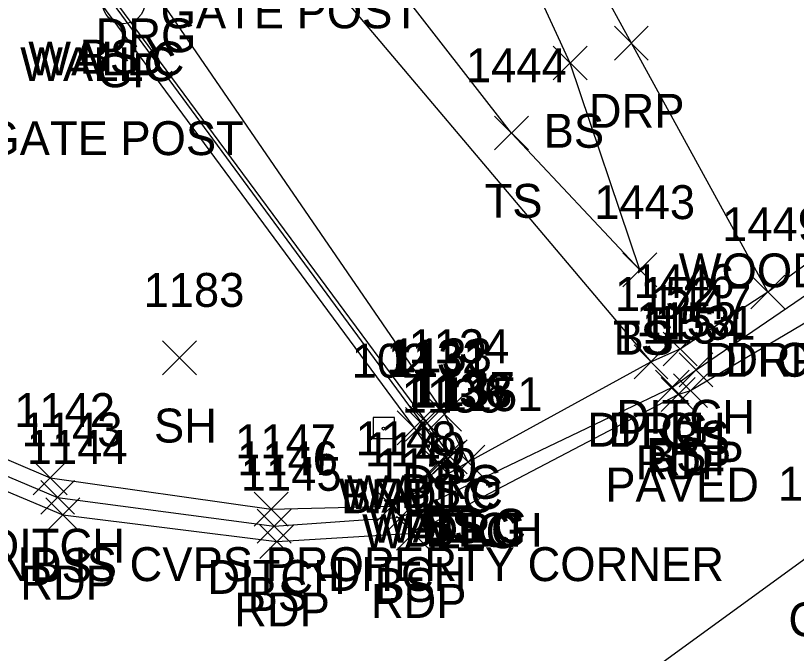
# Model space of a CAD drawing. Extents: x 1647133 to 1649138, y 411736 to 414924.
# Drawn here: x 1648764.25 to 1648810.32, y 412065.88 to 412103.5 of the extents above; entities that cross this region are included whole.
import ezdxf

# ---------------------------------------------------------------- set-up
doc = ezdxf.new("R2010")
doc.units = 0
for name, color, linetype in [('D_A', 7, 'Continuous'), ('D_C', 7, 'Continuous'), ('D_I', 7, 'Continuous'), ('D_TIC', 7, 'Continuous'), ('DD', 7, 'Continuous'), ('L_A', 7, 'Continuous'), ('L_I', 7, 'Continuous'), ('L_TIC', 7, 'Continuous'), ('LELB', 7, 'Continuous'), ('Level 18', 7, 'Continuous'), ('LW', 7, 'Continuous'), ('M_A', 7, 'Continuous'), ('M_C', 7, 'Continuous'), ('M_I', 7, 'Continuous'), ('P_A', 7, 'Continuous'), ('P_I', 7, 'Continuous'), ('P_TIC', 7, 'Continuous'), ('PET', 7, 'Continuous'), ('PRC', 7, 'Continuous'), ('R_A', 7, 'Continuous'), ('R_C', 7, 'Continuous'), ('R_I', 7, 'Continuous'), ('R_TIC', 7, 'Continuous'), ('RDG', 7, 'Continuous'), ('RDP', 7, 'Continuous'), ('RGP', 7, 'Continuous')]:
    doc.layers.add(name, color=color, linetype=linetype)

msp = doc.modelspace()

# ---------------------------------------------------------------- linework, layer by layer
at = {"layer": 'D_TIC'}
for points in [[(1648807.637, 412086.198), (1648809.637, 412088.198)], [(1648809.637, 412086.198), (1648807.637, 412088.198)], [(1648802.463, 412082.836), (1648804.463, 412084.836)], [(1648804.463, 412082.836), (1648802.463, 412084.836)], [(1648802.463, 412082.836), (1648804.463, 412084.836)], [(1648804.463, 412082.836), (1648802.463, 412084.836)], [(1648800.739, 412082.078), (1648802.739, 412084.078)], [(1648802.739, 412082.078), (1648800.739, 412084.078)], [(1648800.739, 412082.078), (1648802.739, 412084.078)], [(1648802.739, 412082.078), (1648800.739, 412084.078)], [(1648789.942, 412076.169), (1648791.942, 412078.169)], [(1648791.942, 412076.169), (1648789.942, 412078.169)], [(1648765.293, 412075.231), (1648767.293, 412077.231)], [(1648767.293, 412075.231), (1648765.293, 412077.231)], [(1648785.441, 412073.562), (1648787.441, 412075.562)], [(1648787.441, 412073.562), (1648785.441, 412075.562)], [(1648778.329, 412073.391), (1648780.329, 412075.391)], [(1648780.329, 412073.391), (1648778.329, 412075.391)]]:
    msp.add_lwpolyline(points, dxfattribs=at)
at = {"layer": 'DD'}
for points in [[(1648700.204, 412133.762), (1648700.854, 412134.053), (1648701.48, 412134.614), (1648714.403, 412119.84), (1648734.341, 412097.427), (1648745.316, 412087.535), (1648753.692, 412081.611), (1648766.293, 412076.231), (1648779.329, 412074.391), (1648786.441, 412074.562), (1648790.942, 412077.169), (1648801.739, 412083.078)], [(1648803.463, 412083.836), (1648808.637, 412087.198), (1648813.917, 412091.05), (1648819.325, 412099.049)], [(1648801.739, 412083.078), (1648803.463, 412083.836)]]:
    msp.add_lwpolyline(points, dxfattribs=at)
at = {"layer": 'L_TIC'}
for points in [[(1648795.966, 412099.703), (1648797.966, 412101.703)], [(1648797.966, 412099.703), (1648795.966, 412101.703)], [(1648792.512, 412095.572), (1648794.512, 412097.572)], [(1648794.512, 412095.572), (1648792.512, 412097.572)], [(1648800.085, 412087.497), (1648802.085, 412089.497)], [(1648802.085, 412087.497), (1648800.085, 412089.497)], [(1648800.085, 412087.497), (1648802.085, 412089.497)], [(1648802.085, 412087.497), (1648800.085, 412089.497)], [(1648772.924, 412082.319), (1648774.924, 412084.319)], [(1648774.924, 412082.319), (1648772.924, 412084.319)], [(1648803.397, 412081.609), (1648805.397, 412083.609)], [(1648805.397, 412081.609), (1648803.397, 412083.609)], [(1648803.397, 412081.609), (1648805.397, 412083.609)], [(1648805.397, 412081.609), (1648803.397, 412083.609)], [(1648802.001, 412080.585), (1648804.001, 412082.585)], [(1648804.001, 412080.585), (1648802.001, 412082.585)], [(1648802.001, 412080.585), (1648804.001, 412082.585)], [(1648804.001, 412080.585), (1648802.001, 412082.585)], [(1648786.771, 412078.188), (1648788.771, 412080.188)], [(1648788.771, 412078.188), (1648786.771, 412080.188)], [(1648787.252, 412078.392), (1648789.252, 412080.392)], [(1648789.252, 412078.392), (1648787.252, 412080.392)], [(1648787.529, 412078.455), (1648789.529, 412080.455)], [(1648789.529, 412078.455), (1648787.529, 412080.455)], [(1648788.611, 412076.412), (1648790.611, 412078.412)], [(1648790.611, 412076.412), (1648788.611, 412078.412)], [(1648788.611, 412076.412), (1648790.611, 412078.412)], [(1648790.611, 412076.412), (1648788.611, 412078.412)], [(1648788.743, 412076.373), (1648790.743, 412078.373)], [(1648790.743, 412076.373), (1648788.743, 412078.373)], [(1648788.895, 412076.48), (1648790.895, 412078.48)], [(1648790.895, 412076.48), (1648788.895, 412078.48)], [(1648788.161, 412076.085), (1648790.161, 412078.085)], [(1648790.161, 412076.085), (1648788.161, 412078.085)], [(1648765.731, 412074.085), (1648767.731, 412076.085)], [(1648767.731, 412074.085), (1648765.731, 412076.085)], [(1648785.989, 412072.92), (1648787.989, 412074.92)], [(1648787.989, 412072.92), (1648785.989, 412074.92)], [(1648778.502, 412072.38), (1648780.502, 412074.38)], [(1648780.502, 412072.38), (1648778.502, 412074.38)]]:
    msp.add_lwpolyline(points, dxfattribs=at)
at = {"layer": 'LELB'}
for points in [[(1648745.05, 412138.635), (1648769.584, 412105.08), (1648788.529, 412079.455), (1648789.895, 412077.48), (1648789.743, 412077.373)], [(1648700.854, 412134.053), (1648713.799, 412119.311), (1648733.781, 412096.829), (1648744.747, 412086.599), (1648753.939, 412080.489), (1648766.731, 412075.085), (1648779.502, 412073.38), (1648786.989, 412073.92), (1648803.001, 412081.585)], [(1648801.085, 412088.497), (1648796.966, 412100.703), (1648790.38, 412115.008), (1648781.189, 412119.025)], [(1648801.085, 412088.497), (1648793.512, 412096.572), (1648781.967, 412111.414), (1648776.578, 412115.68)], [(1648804.397, 412082.609), (1648816.422, 412090.813), (1648820.622, 412097.822)], [(1648803.001, 412081.585), (1648804.397, 412082.609)]]:
    msp.add_lwpolyline(points, dxfattribs=at)
at = {"layer": 'Level 18'}
for p, q in [((1648786.605, 412079.803), (1648785.355, 412079.803)), ((1648785.355, 412079.803), (1648785.355, 412078.553)), ((1648786.605, 412079.803), (1648785.355, 412079.803)), ((1648785.355, 412079.803), (1648785.355, 412078.553)), ((1648786.605, 412078.553), (1648786.605, 412079.803)), ((1648786.605, 412078.553), (1648786.605, 412079.803)), ((1648785.355, 412078.553), (1648786.605, 412078.553)), ((1648785.355, 412078.553), (1648786.605, 412078.553))]:
    msp.add_line(p, q, dxfattribs=at)
msp.add_circle((1648785.956, 412079.14), 0.0833, dxfattribs=at)
at = {"layer": 'LW'}
for points in [[(1648745.173, 412138.304), (1648744.678, 412137.988), (1648768.983, 412104.635), (1648787.771, 412079.188), (1648789.161, 412077.085), (1648789.611, 412077.412)], [(1648745.173, 412138.304), (1648769.46, 412104.966), (1648788.252, 412079.392), (1648789.611, 412077.412)]]:
    msp.add_lwpolyline(points, dxfattribs=at)
at = {"layer": 'P_TIC'}
for points in [[(1648802.342, 412080.153), (1648804.342, 412082.153)], [(1648804.342, 412080.153), (1648802.342, 412082.153)], [(1648802.342, 412080.153), (1648804.342, 412082.153)], [(1648804.342, 412080.153), (1648802.342, 412082.153)], [(1648803.077, 412080.379), (1648805.077, 412082.379)], [(1648805.077, 412080.379), (1648803.077, 412082.379)], [(1648803.077, 412080.379), (1648805.077, 412082.379)], [(1648805.077, 412080.379), (1648803.077, 412082.379)], [(1648766.034, 412073.054), (1648768.034, 412075.054)], [(1648768.034, 412073.054), (1648766.034, 412075.054)], [(1648786.719, 412071.973), (1648788.719, 412073.973)], [(1648788.719, 412071.973), (1648786.719, 412073.973)], [(1648778.661, 412071.471), (1648780.661, 412073.471)], [(1648780.661, 412071.471), (1648778.661, 412073.471)]]:
    msp.add_lwpolyline(points, dxfattribs=at)
at = {"layer": 'PET'}
for points in [[(1648646.814, 412192.55), (1648654.671, 412182.929), (1648666.114, 412172.04), (1648681.295, 412155.026), (1648700.204, 412133.762), (1648713.219, 412118.744), (1648733.101, 412096.235), (1648743.955, 412085.872), (1648754.321, 412079.376), (1648767.034, 412074.054), (1648779.661, 412072.471), (1648787.719, 412072.973), (1648803.342, 412081.153)], [(1648804.077, 412081.379), (1648817.165, 412089.126), (1648824.651, 412094.018), (1648832.497, 412099.297), (1648836.674, 412102.355), (1648842.257, 412096.253), (1648847.201, 412090.123), (1648841.152, 412084.448), (1648829.009, 412072.706), (1648818.716, 412064.019)], [(1648803.342, 412081.153), (1648804.077, 412081.379)]]:
    msp.add_lwpolyline(points, dxfattribs=at)
at = {"layer": 'PRC'}
msp.add_lwpolyline([(1648776.375, 412047.027), (1648793.935, 412059.182), (1648811.415, 412071.887), (1648812.617, 412072.528)], dxfattribs=at)
at = {"layer": 'R_TIC'}
for points in [[(1648799.581, 412100.88), (1648801.581, 412102.88)], [(1648801.581, 412100.88), (1648799.581, 412102.88)], [(1648807.637, 412086.198), (1648809.637, 412088.198)], [(1648809.637, 412086.198), (1648807.637, 412088.198)], [(1648800.739, 412082.078), (1648802.739, 412084.078)], [(1648802.739, 412082.078), (1648800.739, 412084.078)], [(1648788.563, 412078.997), (1648790.563, 412080.997)], [(1648790.563, 412078.997), (1648788.563, 412080.997)], [(1648789.942, 412076.169), (1648791.942, 412078.169)], [(1648791.942, 412076.169), (1648789.942, 412078.169)]]:
    msp.add_lwpolyline(points, dxfattribs=at)
at = {"layer": 'RDG'}
for points in [[(1648665.441, 412272.797), (1648687.368, 412235.883), (1648707.36, 412207.822), (1648732.67, 412172.62), (1648752.06, 412147.321), (1648777.802, 412111.4), (1648801.739, 412083.078)], [(1648657.183, 412267.776), (1648679.811, 412230.814), (1648700.282, 412202.253), (1648725.639, 412167.846), (1648744.327, 412141.94), (1648771.48, 412106.331), (1648789.563, 412079.997), (1648790.942, 412077.169)]]:
    msp.add_lwpolyline(points, dxfattribs=at)
at = {"layer": 'RDP'}
msp.add_lwpolyline([(1648808.637, 412087.198), (1648800.581, 412101.88), (1648792.637, 412116.358), (1648777.478, 412142.603), (1648782.888, 412146.657), (1648798.186, 412123.321), (1648809.106, 412109.222), (1648819.325, 412099.049), (1648820.622, 412097.822), (1648822.814, 412097.685)], dxfattribs=at)
at = {"layer": 'RGP'}
msp.add_circle((1648770.622, 412104.27), 1.25, dxfattribs=at)

# ---------------------------------------------------------------- texts
at = {"layer": 'D_A'}
for p in [(1648804.873, 412082.198), (1648799.699, 412078.836), (1648799.699, 412078.836), (1648797.975, 412078.078), (1648797.975, 412078.078), (1648787.178, 412072.169), (1648762.529, 412071.231), (1648775.565, 412069.391), (1648782.678, 412069.562)]:
    msp.add_text('DITCH', height=2, dxfattribs=at).set_placement(p)
at = {"layer": 'D_C'}
msp.add_text('PAVED', height=2, dxfattribs=at).set_placement((1648799.045, 412074.836))
msp.add_text('PAVED', height=2, dxfattribs=at).set_placement((1648799.045, 412074.836))
at = {"layer": 'D_I'}
for s, p in [('1449', (1648805.936, 412090.198)), ('1446', (1648800.715, 412086.836)), ('1446', (1648800.715, 412086.836)), ('1152', (1648799.613, 412086.078)), ('1152', (1648799.613, 412086.078)), ('1151', (1648789.383, 412080.169)), ('1142', (1648764.167, 412079.231)), ('1147', (1648777.203, 412077.391)), ('1148', (1648784.315, 412077.562))]:
    msp.add_text(s, height=2, dxfattribs=at).set_placement(p)
at = {"layer": 'L_A'}
for s, p in [('WALLC', (1648764.996, 412099.966)), ('BS', (1648768.025, 412100.08)), ('WALLC', (1648764.519, 412099.635)), ('BS', (1648795.407, 412095.703)), ('TS', (1648791.921, 412091.572)), ('TS', (1648799.494, 412083.497)), ('BS', (1648799.526, 412083.497)), ('SH', (1648772.413, 412078.319)), ('BS', (1648802.838, 412077.609)), ('BS', (1648802.838, 412077.609)), ('BS', (1648801.442, 412076.585)), ('BS', (1648801.442, 412076.585)), ('WALLC', (1648783.788, 412074.392)), ('BS', (1648786.97, 412074.455)), ('WALLC', (1648783.306, 412074.188)), ('WALLC', (1648784.696, 412072.085)), ('WALLC', (1648785.147, 412072.412)), ('WALLC', (1648785.147, 412072.412)), ('BS', (1648788.184, 412072.373)), ('BS', (1648788.336, 412072.48)), ('BS', (1648765.172, 412070.085)), ('BS', (1648785.43, 412068.92)), ('BS', (1648777.943, 412068.38))]:
    msp.add_text(s, height=2, dxfattribs=at).set_placement(p)
at = {"layer": 'L_I'}
for s, p in [('1444', (1648790.819, 412099.572)), ('1443', (1648798.392, 412091.497)), ('1443', (1648798.392, 412091.497)), ('1183', (1648771.798, 412086.319)), ('1447', (1648801.704, 412085.609)), ('1447', (1648801.704, 412085.609)), ('1153', (1648800.875, 412084.585)), ('1153', (1648800.875, 412084.585)), ('1132', (1648786.126, 412082.392)), ('1133', (1648786.403, 412082.455)), ('1131', (1648786.212, 412082.188)), ('1136', (1648787.43, 412080.412)), ('1136', (1648787.43, 412080.412)), ('1138', (1648787.617, 412080.373)), ('1137', (1648787.769, 412080.48)), ('1135', (1648787.035, 412080.085)), ('1143', (1648764.605, 412078.085)), ('1149', (1648784.855, 412076.92)), ('1146', (1648777.321, 412076.38))]:
    msp.add_text(s, height=2, dxfattribs=at).set_placement(p)
at = {"layer": 'M_A'}
msp.add_text('BND', height=2, dxfattribs=at).set_placement((1648783.442, 412074.145))
at = {"layer": 'M_C'}
msp.add_text('BND IS CVPS PROPERTY CORNER', height=2, dxfattribs=at).set_placement((1648761.316, 412070.145))
at = {"layer": 'M_I'}
msp.add_text('102', height=2, dxfattribs=at).set_placement((1648784.08, 412082.145))
at = {"layer": 'P_A'}
for s, p in [('RDP', (1648801.565, 412076.379)), ('RDP', (1648801.565, 412076.379)), ('RDP', (1648800.83, 412076.153)), ('RDP', (1648800.83, 412076.153)), ('RDP', (1648764.522, 412069.054)), ('RDP', (1648785.208, 412067.973)), ('RDP', (1648777.149, 412067.471)), ('CR', (1648809.848, 412066.887))]:
    msp.add_text(s, height=2, dxfattribs=at).set_placement(p)
at = {"layer": 'P_I'}
for s, p in [('1154', (1648801.216, 412084.153)), ('1154', (1648801.216, 412084.153)), ('1531', (1648801.951, 412084.379)), ('1531', (1648801.951, 412084.379)), ('1144', (1648764.908, 412077.054)), ('1150', (1648785.507, 412075.973)), ('1145', (1648777.535, 412075.471)), ('1156', (1648809.233, 412074.887))]:
    msp.add_text(s, height=2, dxfattribs=at).set_placement(p)
at = {"layer": 'R_A'}
for s, p in [('DRG', (1648768.968, 412101.331)), ('GP', (1648769.055, 412099.27)), ('DRP', (1648798.07, 412096.88)), ('DRP', (1648806.125, 412082.198)), ('DRG', (1648799.227, 412078.078)), ('DRG', (1648787.051, 412074.997)), ('DRG', (1648788.43, 412072.169))]:
    msp.add_text(s, height=2, dxfattribs=at).set_placement(p)
at = {"layer": 'R_C'}
for s, p in [('GATE POST', (1648772.807, 412102.749)), ('GATE POST', (1648762.41, 412095.27)), ('WOOD POST W/ PLANK RAIL', (1648803.383, 412087.47))]:
    msp.add_text(s, height=2, dxfattribs=at).set_placement(p)
at = {"layer": 'R_I'}
for s, p in [('1449', (1648805.936, 412090.198)), ('1152', (1648799.613, 412086.078)), ('1134', (1648787.437, 412082.997)), ('1151', (1648789.383, 412080.169))]:
    msp.add_text(s, height=2, dxfattribs=at).set_placement(p)

doc.saveas('drawing.dxf')
